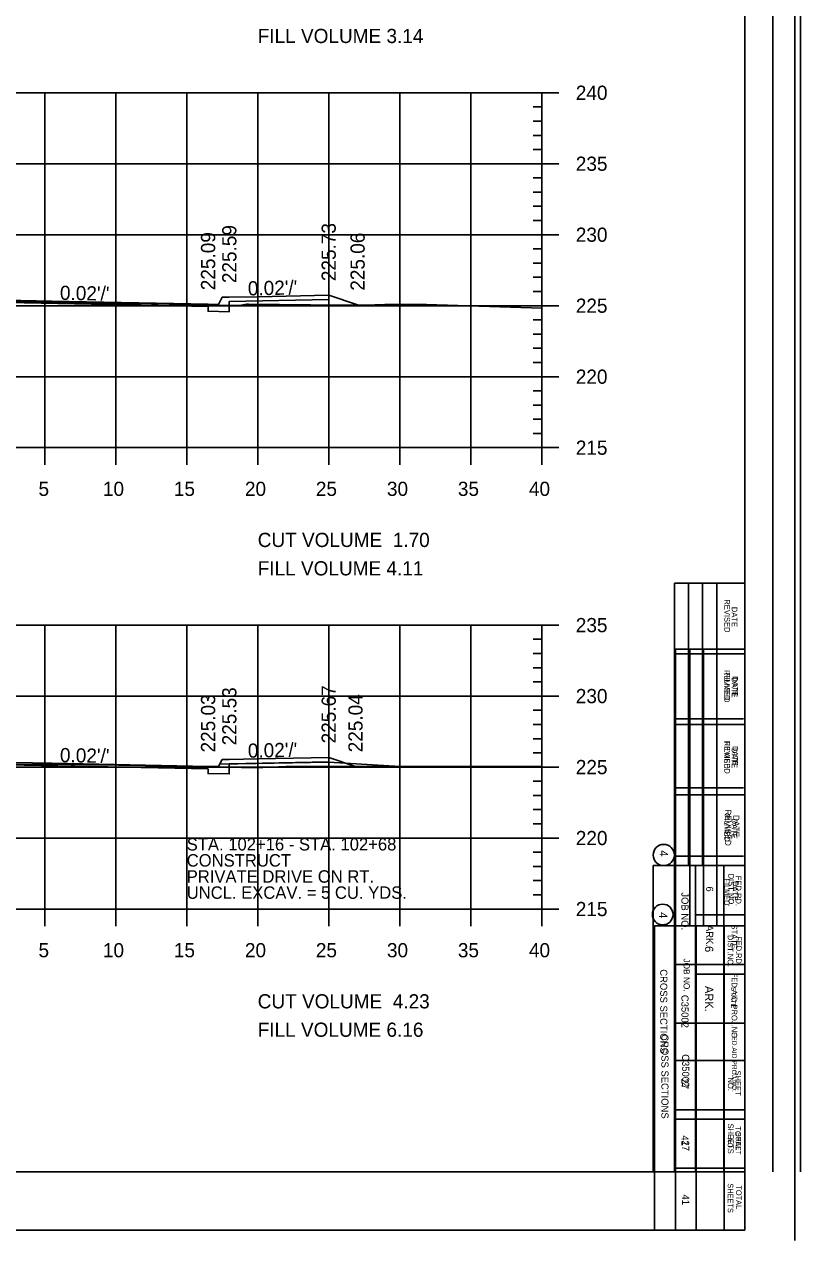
# Model space of a CAD drawing. Extents: x 1367903 to 1373764, y 376865 to 382130.
# Drawn here: x 1370324.2 to 1370433.6, y 377279.1 to 377450.5 of the extents above; entities that cross this region are included whole.
import ezdxf

# ---------------------------------------------------------------- set-up
doc = ezdxf.new("R2010")
doc.units = 0
for name, color, linetype in [('R_Axis', 7, 'Continuous'), ('R_Axis Annot', 7, 'Continuous'), ('R_Border', 7, 'Continuous'), ('R_Border Notes', 7, 'Continuous'), ('R_Border PE', 7, 'Continuous'), ('R_Draft', 7, 'Continuous'), ('R_Drive', 7, 'Continuous'), ('R_Exist Surface', 7, 'Continuous'), ('R_Fin Surface', 7, 'Continuous'), ('R_Fin Surface Annot', 7, 'Continuous'), ('R_Grid', 7, 'Continuous')]:
    doc.layers.add(name, color=color, linetype=linetype)

msp = doc.modelspace()

# ---------------------------------------------------------------- linework, layer by layer
for points in [[(1370281.1, 377412.02), (1370281.1, 377411.36), (1370281.1, 377411.36), (1370281.1, 377409.99), (1370284.1, 377410.05), (1370284.1, 377410.72), (1370317.1, 377411.38), (1370350.1, 377410.72), (1370350.1, 377410.05), (1370353.1, 377409.99), (1370353.1, 377411.44), (1370367.1, 377411.72), (1370367.1, 377412.3)], [(1370281.1, 377346.9), (1370281.1, 377346.23), (1370281.1, 377346.23), (1370281.1, 377344.87), (1370284.1, 377344.93), (1370284.1, 377345.59), (1370317.1, 377346.25), (1370350.1, 377345.59), (1370350.1, 377344.93), (1370353.1, 377344.87), (1370353.1, 377346.31), (1370367.1, 377346.59), (1370367.1, 377347.18)]]:
    msp.add_lwpolyline(points)
at = {"layer": 'R_Axis'}
for p, q in [((1370399.5, 377440.84), (1370394.7, 377440.84)), ((1370397.1, 377390.84), (1370397.1, 377440.84)), ((1370397.1, 377438.84), (1370395.9, 377438.84)), ((1370397.1, 377436.84), (1370395.9, 377436.84)), ((1370397.1, 377434.84), (1370395.9, 377434.84)), ((1370397.1, 377432.84), (1370395.9, 377432.84)), ((1370399.5, 377430.84), (1370394.7, 377430.84)), ((1370397.1, 377428.84), (1370395.9, 377428.84)), ((1370397.1, 377426.84), (1370395.9, 377426.84)), ((1370397.1, 377424.84), (1370395.9, 377424.84)), ((1370397.1, 377422.84), (1370395.9, 377422.84)), ((1370399.5, 377420.84), (1370394.7, 377420.84)), ((1370397.1, 377418.84), (1370395.9, 377418.84)), ((1370397.1, 377416.84), (1370395.9, 377416.84)), ((1370397.1, 377414.84), (1370395.9, 377414.84)), ((1370397.1, 377412.84), (1370395.9, 377412.84)), ((1370399.5, 377410.84), (1370394.7, 377410.84)), ((1370397.1, 377408.84), (1370395.9, 377408.84)), ((1370397.1, 377406.84), (1370395.9, 377406.84)), ((1370397.1, 377404.84), (1370395.9, 377404.84)), ((1370397.1, 377402.84), (1370395.9, 377402.84)), ((1370399.5, 377400.84), (1370394.7, 377400.84)), ((1370397.1, 377398.84), (1370395.9, 377398.84)), ((1370397.1, 377396.84), (1370395.9, 377396.84)), ((1370397.1, 377394.84), (1370395.9, 377394.84)), ((1370327.1, 377388.44), (1370327.1, 377393.24)), ((1370337.1, 377388.44), (1370337.1, 377393.24)), ((1370347.1, 377388.44), (1370347.1, 377393.24)), ((1370357.1, 377388.44), (1370357.1, 377393.24)), ((1370367.1, 377388.44), (1370367.1, 377393.24)), ((1370377.1, 377388.44), (1370377.1, 377393.24)), ((1370387.1, 377388.44), (1370387.1, 377393.24)), ((1370397.1, 377388.44), (1370397.1, 377393.24)), ((1370397.1, 377392.84), (1370395.9, 377392.84)), ((1370237.1, 377390.84), (1370397.1, 377390.84)), ((1370399.5, 377390.84), (1370394.7, 377390.84)), ((1370399.5, 377365.84), (1370394.7, 377365.84)), ((1370397.1, 377325.84), (1370397.1, 377365.84)), ((1370397.1, 377363.84), (1370395.9, 377363.84)), ((1370397.1, 377361.84), (1370395.9, 377361.84)), ((1370397.1, 377359.84), (1370395.9, 377359.84)), ((1370397.1, 377357.84), (1370395.9, 377357.84)), ((1370399.5, 377355.84), (1370394.7, 377355.84)), ((1370397.1, 377353.84), (1370395.9, 377353.84)), ((1370397.1, 377351.84), (1370395.9, 377351.84)), ((1370397.1, 377349.84), (1370395.9, 377349.84)), ((1370397.1, 377347.84), (1370395.9, 377347.84)), ((1370399.5, 377345.84), (1370394.7, 377345.84)), ((1370397.1, 377343.84), (1370395.9, 377343.84)), ((1370397.1, 377341.84), (1370395.9, 377341.84)), ((1370397.1, 377339.84), (1370395.9, 377339.84)), ((1370397.1, 377337.84), (1370395.9, 377337.84)), ((1370399.5, 377335.84), (1370394.7, 377335.84)), ((1370397.1, 377333.84), (1370395.9, 377333.84)), ((1370397.1, 377331.84), (1370395.9, 377331.84)), ((1370397.1, 377329.84), (1370395.9, 377329.84)), ((1370327.1, 377323.44), (1370327.1, 377328.24)), ((1370337.1, 377323.44), (1370337.1, 377328.24)), ((1370347.1, 377323.44), (1370347.1, 377328.24)), ((1370357.1, 377323.44), (1370357.1, 377328.24)), ((1370367.1, 377323.44), (1370367.1, 377328.24)), ((1370377.1, 377323.44), (1370377.1, 377328.24)), ((1370387.1, 377323.44), (1370387.1, 377328.24)), ((1370397.1, 377327.84), (1370395.9, 377327.84)), ((1370397.1, 377323.44), (1370397.1, 377328.24)), ((1370237.1, 377325.84), (1370397.1, 377325.84)), ((1370399.5, 377325.84), (1370394.7, 377325.84))]:
    msp.add_line(p, q, dxfattribs=at)
at = {"layer": 'R_Border'}
for p, q in [((1370432.77, 377620.35), (1370432.77, 377279.12)), ((1370425.73, 377280.59), (1370425.73, 377611.47)), ((1370425.73, 377446.03), (1370425.73, 377446.03)), ((1370415.92, 377280.59), (1370415.92, 377362.43)), ((1370415.92, 377362.43), (1370425.73, 377362.43)), ((1370415.92, 377362.43), (1370417.95, 377362.43)), ((1370417.95, 377362.43), (1370417.95, 377323.46)), ((1370419.9, 377362.43), (1370419.9, 377323.46)), ((1370421.75, 377362.43), (1370421.75, 377323.46)), ((1370415.92, 377352.62), (1370425.53, 377352.62)), ((1370415.92, 377342.9), (1370425.53, 377342.9)), ((1370415.92, 377333.27), (1370425.53, 377333.27)), ((1370425.73, 377323.46), (1370413, 377323.46)), ((1370413, 377323.46), (1370413, 377280.59)), ((1370418.83, 377280.59), (1370418.83, 377323.46)), ((1370422.81, 377280.59), (1370422.81, 377323.46)), ((1370425.73, 377316.65), (1370418.83, 377316.65)), ((1370425.73, 377309.75), (1370415.92, 377309.75)), ((1370425.73, 377296.24), (1370415.92, 377296.24)), ((1370425.73, 377289.33), (1370415.92, 377289.33)), ((1370221.41, 377280.59), (1370425.73, 377280.59))]:
    msp.add_line(p, q, dxfattribs=at)
msp.add_circle((1370414.14, 377325.07), 1.46, dxfattribs=at)
at = {"layer": 'R_Border PE'}
for p, q in [((1370429.65, 377288.8), (1370429.65, 377610.76)), ((1370433.57, 377288.8), (1370433.57, 377610.76)), ((1370425.73, 377603.25), (1370425.73, 377288.8)), ((1370415.78, 377371.74), (1370415.78, 377288.8)), ((1370425.73, 377371.74), (1370415.78, 377371.74)), ((1370417.77, 377371.74), (1370417.77, 377331.96)), ((1370419.76, 377371.74), (1370419.76, 377331.96)), ((1370421.75, 377371.74), (1370421.75, 377331.96)), ((1370425.73, 377361.8), (1370415.78, 377361.8)), ((1370425.73, 377351.85), (1370415.78, 377351.85)), ((1370425.73, 377341.91), (1370415.78, 377341.91)), ((1370425.73, 377331.96), (1370412.8, 377331.96)), ((1370412.8, 377331.96), (1370412.8, 377288.8)), ((1370418.77, 377331.96), (1370418.77, 377288.8)), ((1370422.74, 377331.96), (1370422.74, 377288.8)), ((1370418.83, 377325), (1370425.73, 377325)), ((1370415.91, 377318.04), (1370425.73, 377318.04)), ((1370415.91, 377304.51), (1370425.73, 377304.51)), ((1370415.91, 377297.55), (1370425.73, 377297.55)), ((1370221.41, 377288.8), (1370425.73, 377288.8)), ((1370422.84, 377288.8), (1370422.84, 377288.8))]:
    msp.add_line(p, q, dxfattribs=at)
msp.add_circle((1370414.29, 377333.45), 1.49, dxfattribs=at)
at = {"layer": 'R_Drive'}
for p, q in [((1370351.77, 377346.24), (1370367.1, 377346.54)), ((1370367.1, 377346.54), (1370377.1, 377345.92))]:
    msp.add_line(p, q, dxfattribs=at)
at = {"layer": 'R_Exist Surface'}
for points in [[(1370321.18, 377411.41), (1370336.56, 377411.17), (1370339.72, 377411.14), (1370349.49, 377410.98), (1370350.83, 377410.96), (1370351.05, 377410.94), (1370351.6, 377410.93), (1370352.22, 377410.88), (1370354.76, 377410.93), (1370355.57, 377411.07), (1370355.8, 377411.05), (1370368.89, 377410.92), (1370373.58, 377410.97), (1370374.99, 377411), (1370375.78, 377411.01), (1370380.86, 377410.99), (1370397.1, 377410.48)], [(1370321.42, 377346.27), (1370330.81, 377346.18), (1370333.7, 377346.14), (1370341.25, 377346.07), (1370344.6, 377345.99), (1370354.84, 377345.77), (1370355.32, 377345.77), (1370355.45, 377345.77), (1370357.84, 377345.79), (1370361.09, 377345.91), (1370396.8, 377345.94), (1370397.1, 377345.93)]]:
    msp.add_lwpolyline(points, dxfattribs=at)
at = {"layer": 'R_Fin Surface'}
for points in [[(1370277.72, 377410.9), (1370281.1, 377412.02), (1370282.1, 377412.02), (1370282.6, 377411.02), (1370284.1, 377411.05), (1370306.1, 377411.49), (1370317.1, 377411.71), (1370328.1, 377411.49), (1370350.1, 377411.05), (1370351.6, 377411.02), (1370352.1, 377412.02), (1370353.1, 377412.02), (1370357.1, 377412.1), (1370367.1, 377412.3), (1370371.17, 377410.95)], [(1370277.68, 377345.76), (1370281.1, 377346.9), (1370282.1, 377346.9), (1370282.6, 377345.9), (1370284.1, 377345.93), (1370306.1, 377346.37), (1370317.1, 377346.59), (1370328.1, 377346.37), (1370350.1, 377345.93), (1370351.6, 377345.9), (1370352.1, 377346.9), (1370353.1, 377346.9), (1370357.1, 377346.98), (1370367.1, 377347.18), (1370370.87, 377345.92)]]:
    msp.add_lwpolyline(points, dxfattribs=at)
at = {"layer": 'R_Grid'}
for p, q in [((1370237.1, 377440.84), (1370397.1, 377440.84)), ((1370327.1, 377390.84), (1370327.1, 377440.84)), ((1370337.1, 377390.84), (1370337.1, 377440.84)), ((1370347.1, 377390.84), (1370347.1, 377440.84)), ((1370357.1, 377390.84), (1370357.1, 377440.84)), ((1370367.1, 377390.84), (1370367.1, 377440.84)), ((1370377.1, 377390.84), (1370377.1, 377440.84)), ((1370387.1, 377390.84), (1370387.1, 377440.84)), ((1370397.1, 377390.84), (1370397.1, 377440.84)), ((1370237.1, 377430.84), (1370397.1, 377430.84)), ((1370237.1, 377420.84), (1370397.1, 377420.84)), ((1370237.1, 377410.84), (1370397.1, 377410.84)), ((1370237.1, 377400.84), (1370397.1, 377400.84)), ((1370237.1, 377390.84), (1370397.1, 377390.84)), ((1370237.1, 377365.84), (1370397.1, 377365.84)), ((1370327.1, 377325.84), (1370327.1, 377365.84)), ((1370337.1, 377325.84), (1370337.1, 377365.84)), ((1370347.1, 377325.84), (1370347.1, 377365.84)), ((1370357.1, 377325.84), (1370357.1, 377365.84)), ((1370367.1, 377325.84), (1370367.1, 377365.84)), ((1370377.1, 377325.84), (1370377.1, 377365.84)), ((1370387.1, 377325.84), (1370387.1, 377365.84)), ((1370397.1, 377325.84), (1370397.1, 377365.84)), ((1370237.1, 377355.84), (1370397.1, 377355.84)), ((1370237.1, 377345.84), (1370397.1, 377345.84)), ((1370237.1, 377335.84), (1370397.1, 377335.84)), ((1370237.1, 377325.84), (1370397.1, 377325.84))]:
    msp.add_line(p, q, dxfattribs=at)

# ---------------------------------------------------------------- texts
at = {"layer": 'R_Axis Annot'}
for s, p in [('FILL VOLUME 3.14', (1370357.1, 377447.84)), ('240', (1370401.9, 377439.84)), ('235', (1370401.9, 377429.84)), ('230', (1370401.9, 377419.84)), ('225', (1370401.9, 377409.84)), ('220', (1370401.9, 377399.84)), ('215', (1370401.9, 377389.84)), ('5', (1370326.23, 377384.04)), ('10', (1370335.3, 377384.04)), ('15', (1370345.29, 377384.04)), ('20', (1370355.3, 377384.04)), ('25', (1370365.29, 377384.04)), ('30', (1370375.3, 377384.04)), ('35', (1370385.29, 377384.04)), ('40', (1370395.3, 377384.04)), ('CUT VOLUME  1.70', (1370357.1, 377376.84)), ('FILL VOLUME 4.11', (1370357.1, 377372.84)), ('235', (1370401.9, 377364.84)), ('230', (1370401.9, 377354.84)), ('225', (1370401.9, 377344.84)), ('220', (1370401.9, 377334.84)), ('215', (1370401.9, 377324.84)), ('5', (1370326.23, 377319.04)), ('10', (1370335.3, 377319.04)), ('15', (1370345.29, 377319.04)), ('20', (1370355.3, 377319.04)), ('25', (1370365.29, 377319.04)), ('30', (1370375.3, 377319.04)), ('35', (1370385.29, 377319.04)), ('40', (1370395.3, 377319.04)), ('CUT VOLUME  4.23', (1370357.1, 377311.84)), ('FILL VOLUME 6.16', (1370357.1, 377307.84))]:
    msp.add_text(s, height=2, dxfattribs=at).set_placement(p)
at = {"layer": 'R_Border'}
for s, height, p in [('REVISED', 0.778, (1370422.81, 377359.51)), ('DATE', 0.778, (1370423.98, 377358.64)), ('FILMED', 0.778, (1370422.81, 377349.41)), ('DATE', 0.778, (1370423.98, 377348.82)), ('REVISED', 0.875, (1370422.91, 377339.88)), ('DATE', 0.875, (1370424.08, 377339.1)), ('FILMED', 0.778, (1370422.81, 377330.16)), ('DATE', 0.778, (1370423.98, 377329.77)), ('4', 1.17, (1370413.62, 377325.4)), ('DIST.NO.', 0.778, (1370423.3, 377322.19)), ('FED.RD.', 0.778, (1370424.47, 377321.99)), ('6', 1.17, (1370420.09, 377320.63)), ('JOB NO.', 0.875, (1370417.08, 377318.88)), ('ARK.', 1.166, (1370420.09, 377315)), ('STATE', 0.681, (1370423.78, 377314.9)), ('FED.AID PROJ.NO.', 0.6805, (1370423.89, 377308.49)), ('SHEET', 0.681, (1370424.47, 377294.39)), ('NO.', 0.681, (1370423.3, 377293.61)), ('SHEETS', 0.778, (1370423.3, 377287.2)), ('TOTAL', 0.778, (1370424.47, 377286.91))]:
    msp.add_text(s, height=height, rotation=270, dxfattribs=at).set_placement(p)
at = {"layer": 'R_Border Notes'}
for s, height, p in [('CROSS SECTIONS', 0.9945, (1370413.96, 377308.2)), ('C35002', 0.995, (1370416.88, 377305.39)), ('27', 0.995, (1370416.88, 377293.23)), ('41', 0.995, (1370416.88, 377285.62))]:
    msp.add_text(s, height=height, rotation=270, dxfattribs=at).set_placement(p)
at = {"layer": 'R_Border PE'}
for s, height, p in [('REVISED', 0.796, (1370422.83, 377369.47)), ('DATE', 0.796, (1370423.86, 377368.41)), ('FILMED', 0.796, (1370422.83, 377359.12)), ('DATE', 0.796, (1370423.86, 377358.47)), ('REVISED', 0.796, (1370422.83, 377349.57)), ('DATE', 0.796, (1370423.86, 377348.52)), ('FILMED', 0.796, (1370422.83, 377339.23)), ('DATE', 0.796, (1370423.86, 377338.58)), ('4', 1.19, (1370413.69, 377334.12)), ('DIST.NO.', 0.796, (1370423.4, 377330.83)), ('FED.RD.', 0.796, (1370424.43, 377330.52)), ('JOB NO.', 0.995, (1370416.78, 377328.19)), ('6', 0.995, (1370420.26, 377329.02)), ('ARK.', 0.995, (1370420.26, 377323.6)), ('STATE', 0.796, (1370423.84, 377323.66)), ('CROSS SECTIONS', 0.9945, (1370413.79, 377317.35)), ('FED.AID PROJ.NO.', 0.7956, (1370423.84, 377316.88)), ('C35002', 0.995, (1370416.78, 377313.75)), ('SHEET', 0.796, (1370424.35, 377303.09)), ('27', 0.995, (1370416.78, 377301.96)), ('NO.', 0.796, (1370423.32, 377302.11)), ('SHEETS', 0.796, (1370423.32, 377295.62)), ('41', 0.995, (1370416.78, 377293.96)), ('TOTAL', 0.796, (1370424.35, 377295.23))]:
    msp.add_text(s, height=height, rotation=270, dxfattribs=at).set_placement(p)
at = {"layer": 'R_Draft'}
for s, p in [('STA. 102+16 - STA. 102+68', (1370347.1, 377334.09)), ('CONSTRUCT', (1370347.1, 377331.82)), ('PRIVATE DRIVE ON RT.', (1370347.1, 377329.55)), ('UNCL. EXCAV. = 5 CU. YDS.', (1370347.1, 377327.28))]:
    msp.add_text(s, height=1.75, dxfattribs=at).set_placement(p)
at = {"layer": 'R_Fin Surface Annot'}
for s, rotation, p in [('225.59', 90, (1370354.1, 377414.02)), ('225.73', 90, (1370368.1, 377414.3)), ('225.09', 90, (1370351.11, 377413.02)), ('225.06', 90, (1370372.17, 377412.95)), ("0.02'/'", 358.8542, (1370329.23, 377411.67)), ("0.02'/'", 1.1458, (1370355.73, 377412.28)), ('225.53', 90, (1370354.1, 377348.9)), ('225.67', 90, (1370368.1, 377349.18)), ('225.03', 90, (1370351.11, 377347.9)), ('225.04', 90, (1370371.87, 377347.92)), ("0.02'/'", 358.8542, (1370329.23, 377346.54)), ("0.02'/'", 1.1458, (1370355.73, 377347.15))]:
    msp.add_text(s, height=2, rotation=rotation, dxfattribs=at).set_placement(p)

doc.saveas('drawing.dxf')
